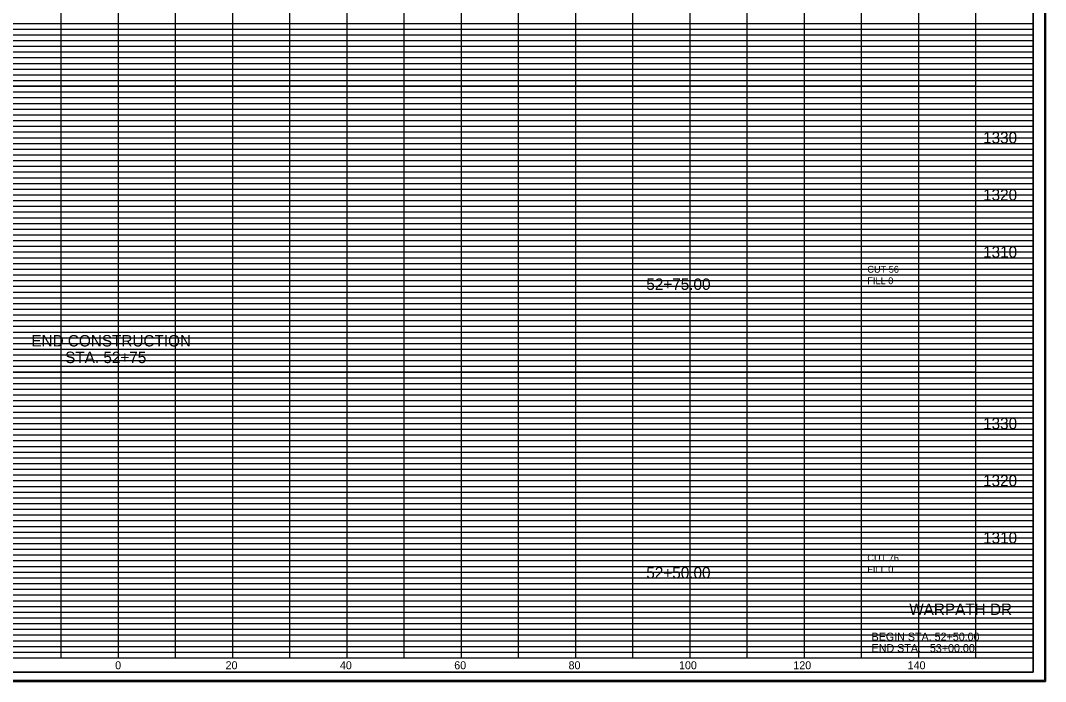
# Model space of a CAD drawing. Extents: x 130 to 1324, y -58 to 2657.
# Drawn here: x 1142.9 to 1322.2, y 1265.9 to 1381.5 of the extents above; entities that cross this region are included whole.
import ezdxf

# ---------------------------------------------------------------- set-up
doc = ezdxf.new("R2010")
doc.units = 0
for name, color, linetype in [('DESIGN - SCRATCH - User 2', 7, 'Continuous'), ('DESIGN - SHEET - Corner Text', 7, 'Continuous'), ('DESIGN - SHEET - Light Grid', 7, 'Continuous'), ('DESIGN - SHEET - Linework', 7, 'Continuous'), ('DESIGN - SHEET - Plot Shape', 7, 'Continuous'), ('DESIGN - TYPICAL - Finished Grade and Subgrade', 7, 'Continuous'), ('DESIGN - TYPICAL - Text', 7, 'Continuous')]:
    doc.layers.add(name, color=color, linetype=linetype)

# ---------------------------------------------------------------- blocks, each defined once
blk = doc.blocks.new('XSTSHT')
at = {"layer": 'DESIGN - SHEET - Light Grid'}
for p, q in [((8, 11.1), (16, 11.1)), ((16, 11.1), (24, 11.1)), ((24, 11.1), (32, 11.1)), ((8, 10.9), (16, 10.9)), ((8, 10.8), (16, 10.8)), ((16, 10.9), (24, 10.9)), ((16, 10.8), (24, 10.8)), ((24, 10.9), (32, 10.9)), ((24, 10.8), (32, 10.8)), ((8, 10.7), (16, 10.7)), ((8, 10.6), (16, 10.6)), ((16, 10.7), (24, 10.7)), ((16, 10.6), (24, 10.6)), ((24, 10.7), (32, 10.7)), ((24, 10.6), (32, 10.6)), ((8, 10.5), (16, 10.5)), ((8, 10.4), (16, 10.4)), ((16, 10.5), (24, 10.5)), ((16, 10.4), (24, 10.4)), ((24, 10.5), (32, 10.5)), ((24, 10.4), (32, 10.4)), ((8, 10.3), (16, 10.3)), ((16, 10.3), (24, 10.3)), ((24, 10.3), (32, 10.3)), ((8, 10.2), (16, 10.2)), ((8, 10.1), (16, 10.1)), ((16, 10.2), (24, 10.2)), ((16, 10.1), (24, 10.1)), ((24, 10.2), (32, 10.2)), ((24, 10.1), (32, 10.1)), ((8, 9.9), (16, 9.9)), ((16, 9.9), (24, 9.9)), ((24, 9.9), (32, 9.9)), ((8, 9.8), (16, 9.8)), ((8, 9.7), (16, 9.7)), ((16, 9.8), (24, 9.8)), ((16, 9.7), (24, 9.7)), ((24, 9.8), (32, 9.8)), ((24, 9.7), (32, 9.7)), ((8, 9.6), (16, 9.6)), ((16, 9.6), (24, 9.6)), ((24, 9.6), (32, 9.6)), ((8, 9.5), (16, 9.5)), ((8, 9.4), (16, 9.4)), ((16, 9.5), (24, 9.5)), ((16, 9.4), (24, 9.4)), ((24, 9.5), (32, 9.5)), ((24, 9.4), (32, 9.4)), ((8, 9.3), (16, 9.3)), ((8, 9.2), (16, 9.2)), ((16, 9.3), (24, 9.3)), ((16, 9.2), (24, 9.2)), ((24, 9.3), (32, 9.3)), ((24, 9.2), (32, 9.2)), ((8, 9.1), (16, 9.1)), ((16, 9.1), (24, 9.1)), ((24, 9.1), (32, 9.1)), ((8, 8.9), (16, 8.9)), ((8, 8.8), (16, 8.8)), ((16, 8.9), (24, 8.9)), ((16, 8.8), (24, 8.8)), ((24, 8.9), (32, 8.9)), ((24, 8.8), (32, 8.8)), ((8, 8.7), (16, 8.7)), ((16, 8.7), (24, 8.7)), ((24, 8.7), (32, 8.7)), ((8, 8.6), (16, 8.6)), ((8, 8.5), (16, 8.5)), ((16, 8.6), (24, 8.6)), ((16, 8.5), (24, 8.5)), ((24, 8.6), (32, 8.6)), ((24, 8.5), (32, 8.5)), ((8, 8.4), (16, 8.4)), ((8, 8.3), (16, 8.3)), ((16, 8.4), (24, 8.4)), ((16, 8.3), (24, 8.3)), ((24, 8.4), (32, 8.4)), ((24, 8.3), (32, 8.3)), ((8, 8.2), (16, 8.2)), ((8, 8.1), (16, 8.1)), ((16, 8.2), (24, 8.2)), ((16, 8.1), (24, 8.1)), ((24, 8.2), (32, 8.2)), ((24, 8.1), (32, 8.1)), ((8, 7.9), (16, 7.9)), ((16, 7.9), (24, 7.9)), ((24, 7.9), (32, 7.9)), ((8, 7.8), (16, 7.8)), ((16, 7.8), (24, 7.8)), ((24, 7.8), (32, 7.8)), ((8, 7.7), (16, 7.7)), ((8, 7.6), (16, 7.6)), ((16, 7.7), (24, 7.7)), ((16, 7.6), (24, 7.6)), ((24, 7.7), (32, 7.7)), ((24, 7.6), (32, 7.6)), ((8, 7.5), (16, 7.5)), ((8, 7.4), (16, 7.4)), ((16, 7.5), (24, 7.5)), ((16, 7.4), (24, 7.4)), ((24, 7.5), (32, 7.5)), ((24, 7.4), (32, 7.4)), ((8, 7.3), (16, 7.3)), ((8, 7.2), (16, 7.2)), ((16, 7.3), (24, 7.3)), ((16, 7.2), (24, 7.2)), ((24, 7.3), (32, 7.3)), ((24, 7.2), (32, 7.2)), ((8, 7.1), (16, 7.1)), ((16, 7.1), (24, 7.1)), ((24, 7.1), (32, 7.1)), ((8, 6.9), (16, 6.9)), ((16, 6.9), (24, 6.9)), ((24, 6.9), (32, 6.9)), ((8, 6.8), (16, 6.8)), ((8, 6.7), (16, 6.7)), ((16, 6.8), (24, 6.8)), ((16, 6.7), (24, 6.7)), ((24, 6.8), (32, 6.8)), ((24, 6.7), (32, 6.7)), ((8, 6.6), (16, 6.6)), ((8, 6.5), (16, 6.5)), ((16, 6.6), (24, 6.6)), ((16, 6.5), (24, 6.5)), ((24, 6.6), (32, 6.6)), ((24, 6.5), (32, 6.5)), ((8, 6.4), (16, 6.4)), ((8, 6.3), (16, 6.3)), ((16, 6.4), (24, 6.4)), ((16, 6.3), (24, 6.3)), ((24, 6.4), (32, 6.4)), ((24, 6.3), (32, 6.3)), ((8, 6.2), (16, 6.2)), ((8, 6.1), (16, 6.1)), ((16, 6.2), (24, 6.2)), ((16, 6.1), (24, 6.1)), ((24, 6.2), (32, 6.2)), ((24, 6.1), (32, 6.1)), ((8, 5.9), (16, 5.9)), ((8, 5.8), (16, 5.8)), ((16, 5.9), (24, 5.9)), ((16, 5.8), (24, 5.8)), ((24, 5.9), (32, 5.9)), ((24, 5.8), (32, 5.8)), ((8, 5.7), (16, 5.7)), ((8, 5.6), (16, 5.6)), ((16, 5.7), (24, 5.7)), ((16, 5.6), (24, 5.6)), ((24, 5.7), (32, 5.7)), ((24, 5.6), (32, 5.6)), ((8, 5.5), (16, 5.5)), ((8, 5.4), (16, 5.4)), ((16, 5.5), (24, 5.5)), ((16, 5.4), (24, 5.4)), ((24, 5.5), (32, 5.5)), ((24, 5.4), (32, 5.4)), ((8, 5.3), (16, 5.3)), ((8, 5.2), (16, 5.2)), ((16, 5.3), (24, 5.3)), ((16, 5.2), (24, 5.2)), ((24, 5.3), (32, 5.3)), ((24, 5.2), (32, 5.2)), ((8, 5.1), (16, 5.1)), ((16, 5.1), (24, 5.1)), ((24, 5.1), (32, 5.1)), ((8, 4.9), (16, 4.9)), ((16, 4.9), (24, 4.9)), ((24, 4.9), (32, 4.9)), ((8, 4.8), (16, 4.8)), ((8, 4.7), (16, 4.7)), ((16, 4.8), (24, 4.8)), ((16, 4.7), (24, 4.7)), ((24, 4.8), (32, 4.8)), ((24, 4.7), (32, 4.7)), ((8, 4.6), (16, 4.6)), ((8, 4.5), (16, 4.5)), ((16, 4.6), (24, 4.6)), ((16, 4.5), (24, 4.5)), ((24, 4.6), (32, 4.6)), ((24, 4.5), (32, 4.5)), ((8, 4.4), (16, 4.4)), ((16, 4.4), (24, 4.4)), ((24, 4.4), (32, 4.4)), ((8, 4.3), (16, 4.3)), ((8, 4.2), (16, 4.2)), ((16, 4.3), (24, 4.3)), ((16, 4.2), (24, 4.2)), ((24, 4.3), (32, 4.3)), ((24, 4.2), (32, 4.2)), ((8, 4.1), (16, 4.1)), ((16, 4.1), (24, 4.1)), ((24, 4.1), (32, 4.1)), ((8, 3.9), (16, 3.9)), ((8, 3.8), (16, 3.8)), ((16, 3.9), (24, 3.9)), ((16, 3.8), (24, 3.8)), ((24, 3.9), (32, 3.9)), ((24, 3.8), (32, 3.8)), ((8, 3.7), (16, 3.7)), ((8, 3.6), (16, 3.6)), ((16, 3.7), (24, 3.7)), ((16, 3.6), (24, 3.6)), ((24, 3.7), (32, 3.7)), ((24, 3.6), (32, 3.6)), ((8, 3.5), (16, 3.5)), ((16, 3.5), (24, 3.5)), ((24, 3.5), (32, 3.5)), ((8, 3.4), (16, 3.4)), ((8, 3.3), (16, 3.3)), ((16, 3.4), (24, 3.4)), ((16, 3.3), (24, 3.3)), ((24, 3.4), (32, 3.4)), ((24, 3.3), (32, 3.3)), ((8, 3.2), (16, 3.2)), ((8, 3.1), (16, 3.1)), ((16, 3.2), (24, 3.2)), ((16, 3.1), (24, 3.1)), ((24, 3.2), (32, 3.2)), ((24, 3.1), (32, 3.1)), ((8, 2.9), (16, 2.9)), ((16, 2.9), (24, 2.9)), ((24, 2.9), (32, 2.9)), ((8, 2.8), (16, 2.8)), ((8, 2.7), (16, 2.7)), ((16, 2.8), (24, 2.8)), ((16, 2.7), (24, 2.7)), ((24, 2.8), (32, 2.8)), ((24, 2.7), (32, 2.7)), ((8, 2.6), (16, 2.6)), ((16, 2.6), (24, 2.6)), ((24, 2.6), (32, 2.6)), ((8, 2.5), (16, 2.5)), ((8, 2.4), (16, 2.4)), ((16, 2.5), (24, 2.5)), ((16, 2.4), (24, 2.4)), ((24, 2.5), (32, 2.5)), ((24, 2.4), (32, 2.4)), ((8, 2.3), (16, 2.3)), ((8, 2.2), (16, 2.2)), ((16, 2.3), (24, 2.3)), ((16, 2.2), (24, 2.2)), ((24, 2.3), (32, 2.3)), ((24, 2.2), (32, 2.2)), ((8, 2.1), (16, 2.1)), ((16, 2.1), (24, 2.1)), ((24, 2.1), (32, 2.1)), ((8, 1.9), (16, 1.9)), ((8, 1.8), (16, 1.8)), ((16, 1.9), (24, 1.9)), ((16, 1.8), (24, 1.8)), ((24, 1.9), (32, 1.9)), ((24, 1.8), (32, 1.8)), ((8, 1.7), (16, 1.7)), ((16, 1.7), (24, 1.7)), ((24, 1.7), (32, 1.7)), ((8, 1.6), (16, 1.6)), ((8, 1.5), (16, 1.5)), ((16, 1.6), (24, 1.6)), ((16, 1.5), (24, 1.5)), ((24, 1.6), (32, 1.6)), ((24, 1.5), (32, 1.5)), ((8, 1.4), (16, 1.4)), ((8, 1.3), (16, 1.3)), ((16, 1.4), (24, 1.4)), ((16, 1.3), (24, 1.3)), ((24, 1.4), (32, 1.4)), ((24, 1.3), (32, 1.3)), ((8, 1.2), (16, 1.2)), ((8, 1.1), (16, 1.1)), ((16, 1.2), (24, 1.2)), ((16, 1.1), (24, 1.1)), ((24, 1.2), (32, 1.2)), ((24, 1.1), (32, 1.1)), ((8, 0.9), (16, 0.9)), ((16, 0.9), (24, 0.9)), ((24, 0.9), (32, 0.9)), ((8, 0.8), (16, 0.8)), ((16, 0.8), (24, 0.8)), ((24, 0.8), (32, 0.8)), ((8, 0.7), (16, 0.7)), ((8, 0.6), (16, 0.6)), ((16, 0.7), (24, 0.7)), ((16, 0.6), (24, 0.6)), ((24, 0.7), (32, 0.7)), ((24, 0.6), (32, 0.6)), ((8, 0.5), (16, 0.5)), ((8, 0.4), (16, 0.4)), ((16, 0.5), (24, 0.5)), ((16, 0.4), (24, 0.4)), ((24, 0.5), (32, 0.5)), ((24, 0.4), (32, 0.4)), ((8, 0.3), (16, 0.3)), ((8, 0.2), (16, 0.2)), ((16, 0.3), (24, 0.3)), ((16, 0.2), (24, 0.2)), ((24, 0.3), (32, 0.3)), ((24, 0.2), (32, 0.2)), ((8, 0.1), (16, 0.1)), ((16, 0.1), (24, 0.1)), ((24, 0.1), (32, 0.1))]:
    blk.add_line(p, q, dxfattribs=at)
at = {"layer": 'DESIGN - SHEET - Linework'}
for p, q in [((32.217, 21.414), (32.217, -0.414)), ((15, 0), (15, 21)), ((16, 0), (16, 21)), ((17, 0), (17, 21)), ((18, 0), (18, 21)), ((19, 0), (19, 21)), ((20, 0), (20, 21)), ((21, 0), (21, 21)), ((22, 0), (22, 21)), ((23, 0), (23, 21)), ((24, 0), (24, 21)), ((25, 0), (25, 21)), ((26, 0), (26, 21)), ((27, 0), (27, 21)), ((28, 0), (28, 20)), ((29, 0), (29, 20)), ((30, 0), (30, 20)), ((31, 0), (31, 20)), ((0, 11), (32, 11)), ((0, 10), (32, 10)), ((0, 9), (32, 9)), ((0, 8), (32, 8)), ((0, 7), (32, 7)), ((0, 6), (32, 6)), ((0, 5), (32, 5)), ((0, 4), (32, 4)), ((0, 3), (32, 3)), ((0, 2), (32, 2)), ((0, 1), (32, 1)), ((-1.823, -0.414), (32.217, -0.414))]:
    blk.add_line(p, q, dxfattribs=at)
blk.add_lwpolyline([(0, 21), (0, 0), (32, 0), (32, 21), (0, 21)], dxfattribs=at)
at = {"layer": 'DESIGN - SHEET - Plot Shape'}
for points in [[(-1.803, 21.394), (32.197, 21.394), (32.197, -0.394), (-1.803, -0.394)], [(-0.85, 21), (32, 21), (32, -0.25), (-0.85, -0.25)]]:
    blk.add_lwpolyline(points, close=True, dxfattribs=at)

msp = doc.modelspace()

# ---------------------------------------------------------------- linework, layer by layer
at = {"layer": 'DESIGN - SCRATCH - User 2'}
for points in [[(1010, 1330), (1310, 1330), (1310, 1370), (1010, 1370)], [(1010, 1280), (1310, 1280), (1310, 1320), (1010, 1320)]]:
    msp.add_lwpolyline(points, close=True, dxfattribs=at)
at = {"layer": 'DESIGN - SHEET - Plot Shape'}
msp.add_lwpolyline([(991.5, 1267.5), (1320, 1267.5), (1320, 1480), (991.5, 1480)], close=True, dxfattribs=at)

# ---------------------------------------------------------------- block references
at = {"layer": 'DESIGN - TYPICAL - Finished Grade and Subgrade', "xscale": 10, "yscale": 10}
msp.add_blockref('XSTSHT', (1000, 1270), dxfattribs=at)

# ---------------------------------------------------------------- texts
at = {"layer": 'DESIGN - SHEET - Corner Text'}
for s, height, p in [('1330', 2, (1311.25, 1360)), ('1320', 2, (1311.25, 1350)), ('1310', 2, (1311.25, 1340)), ('52+75.00', 2, (1252.34, 1334.37)), ('1330', 2, (1311.25, 1310)), ('1320', 2, (1311.25, 1300)), ('1310', 2, (1311.25, 1290)), ('52+50.00', 2, (1252.34, 1283.89)), ('WARPATH DR', 2, (1298.34, 1277.5)), ('BEGIN STA. 52+50.00', 1.4, (1291.75, 1273)), ('END STA.   53+00.00', 1.4, (1291.75, 1271)), ('0', 1.4, (1159.42, 1268)), ('0', 1.4, (1159.42, 1268)), ('20', 1.4, (1178.74, 1268)), ('40', 1.4, (1198.74, 1268)), ('60', 1.4, (1218.74, 1268)), ('80', 1.4, (1238.74, 1268)), ('100', 1.4, (1258.06, 1268)), ('120', 1.4, (1278.06, 1268)), ('140', 1.4, (1298.06, 1268))]:
    msp.add_text(s, height=height, dxfattribs=at).set_placement(p)
at = {"layer": 'DESIGN - TYPICAL - Text'}
for s, height, p in [('CUT 56', 1.2, (1291, 1337.37)), ('FILL 0', 1.2, (1291, 1335.37)), ('END CONSTRUCTION', 2, (1144.76, 1324.47)), ('STA. 52+75', 2, (1150.67, 1321.57)), ('CUT 76', 1.2, (1291, 1286.89)), ('FILL 0', 1.2, (1291, 1284.89))]:
    msp.add_text(s, height=height, dxfattribs=at).set_placement(p)

doc.saveas('drawing.dxf')
